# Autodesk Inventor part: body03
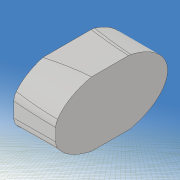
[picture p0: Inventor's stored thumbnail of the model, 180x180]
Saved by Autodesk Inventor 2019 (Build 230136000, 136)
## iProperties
Created: 2020-12
Part Number: body03
Material: 一般
Document SubType Name: Modeling
Designer: kikut
Density: 1 g/cm^3
Appearance: 既定
Mass: 87.6477 g
Surface Area: 156.124 cm^2
Volume: 87.6477 cm^3
Author: kikut
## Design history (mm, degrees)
sketch "スケッチ1"
  geometry: L1 (-100, -20)-(100, -20); L2 (100, -20)-(100, 20); L3 (100, 20)-(-100, 20); L4 (-100, 20)-(-100, -20); L5 (-100, -20)-(100, 20); L6 (100, -20)-(-100, 20); 1 further point
  constraints: 12 end point, 2 midpoint, 2 parallel, 1 horizontal, 1 perpendicular
  dimensions: "d0" = 40 distance of L3.end L1.start; "d1" = 200 distance of L2.end L3.end
extrude "押し出し1" new body sketch "スケッチ1" stored distance "d2" = 60; taper "d3" = 0 deg
sketch "スケッチ2"
  geometry: L1 (0, -60)-(0, 0) reference; L2 (200, -60)-(200, 0) reference; L3 (0, 0)-(200, 0) reference; L4 (200, -60)-(0, -60) reference; L5 (0, -26)-(0, -32); L6 (194, -10)-(194, -13); L7 (194, -13)-(174, -33); L8 (174, -33)-(200, -58); L9 (-20, 20)-(220, 20); L10 (220, 20)-(220, -100); L11 (220, -100)-(-20, -100); L12 (-20, -100)-(-20, 20); 12 further points
  constraints: 16 end point, 4 point on line, 2 parallel, 2 vertical, 1 horizontal, 1 perpendicular, 14 other
  dimensions: "d4" = 32 distance from line of point (32, -12) L1; "d5" = 50 horizontal distance of point (32, -12) point (82, -11); "d6" = 50 horizontal distance of point (132, -17) point (82, -11); "d7" = 12 distance from line of point (32, -12) L3; "d8" = 11 distance from line of point (82, -11) L3; "d10" = 17 distance from line of point (132, -17) L3; "d11" = 26 distance from line of L5.start L3; "d12" = 0 distance from line of point (200, -60) L4; "d13" = 28 distance from line of L5.end L4; "d14" = 12 distance from line of point (28, -48) L4; "d15" = 10 distance from line of point (80, -50) L4; "d16" = 16 distance from line of point (130, -44) L4; "d17" = 28 distance from line of point (28, -48) L1; "d19" = 50 horizontal distance of point (130, -44) point (80, -50); "d20" = 80 distance from line of point (80, -50) L1; "d21" = 6 distance from line of L6.start L2; "d22" = 36 distance from line of point (164, -24) L2; "d23" = 24 distance from line of point (176, -20) L2; "d24" = 10 distance from line of L6.start L3; "d25" = 20 distance from line of point (176, -20) L3; "d26" = 24 distance from line of point (164, -24) L3; "d27" = 40 distance from line of point (160, -40) L2; "d28" = 25 distance from line of point (175, -47.5) L2; "d29" = 12.5 distance from line of point (175, -47.5) L4; "d30" = 20 distance from line of L4 point (160, -40); "d31" = 3 distance of L6.start L6.end; "d32" = 33 distance from line of L7.end L3; "d33" = 26 distance from line of L7.end L2; "d34" = 2 distance of L8.end L2.start; "d35" = 120 distance of L11.end L9.start; "d36" = 240 distance of L10.end L11.end; "d37" = 20 distance between parallel lines of L1 L12; "d38" = 20 distance between parallel lines of L3 L9
extrude "押し出し2" cut sketch "スケッチ2" extent not by distance; stored distance "d39" = 0.02; taper "d40" = 0 deg
sketch "スケッチ8"
  geometry: L1 (-100, -20)-(-100, 20) reference; L2 (100, 20)-(100, -20) reference; L3 (-142.805, 0)-(142.831, 0) reference; L4 (110, 30)-(-110, 30); L5 (-110, 30)-(-110, -30); L6 (-110, -30)-(110, -30); L7 (110, -30)-(110, 30); L8 (110, 30)-(-110, -30); L9 (-110, 30)-(110, -30); L10 (-100, -2)-(-100, 2); L11 (100, -3)-(100, 3); 7 further points
  constraints: 16 end point, 4 point on line, 2 midpoint, 2 parallel, 2 perpendicular, 1 collinear, 1 horizontal, 10 other
  dimensions: "d93" = 2 vertical distance of point (0, 0) L10.end; "d94" = 2 vertical distance of L10.start point (0, 0); "d95" = 35 distance from line of point (-65, -10) L1; "d96" = 0 horizontal distance of point (-65, 10) point (-65, -10); "d97" = 10 vertical distance of point (0, 0) point (-65, -10); "d98" = 10 vertical distance of point (-65, 10) point (0, 0); "d99" = 100 distance from line of point (0, -10) L1; "d100" = 0 horizontal distance of point (0, 10) point (0, -10); "d101" = 10 distance of point (0, -10) point (0, 0); "d102" = 10 distance of point (0, 0) point (0, 10); "d103" = 160 distance from line of point (60, -4) L1; "d104" = 0 horizontal distance of point (60, 4) point (60, -4); "d105" = 4 distance from line of L3 point (60, -4); "d106" = 4 distance from line of L3 point (60, 4); "d107" = 3 distance from line of L11.start L3; "d108" = 3 distance from line of L11.end L3; "d109" = 220 distance of L5.end L6.end; "d110" = 60 distance of L4.end L5.end
extrude "押し出し6" cut sketch "スケッチ8" extent not by distance; stored distance "d111" = 10; taper "d112" = 0 deg
sketch "スケッチ9" dims "d113" = 20, "d114" = 12
  geometry: L1 (-29, -18)-(21, -18); L2 (21, -18)-(21, 22); L3 (21, 22)-(-29, 22); L4 (-29, 22)-(-29, -18); L5 (-29, -18)-(21, 22); L6 (21, -18)-(-29, 22); 2 further points; 1 other entity
  constraints: 12 end point, 2 midpoint, 2 parallel, 1 coincident, 1 horizontal, 1 perpendicular, 2 other
  dimensions: "d115" = 50 distance of L2.end L3.end; "d116" = 40 distance of L1.end L2.end
extrude "押し出し7" cut sketch "スケッチ9" distance "d117" = 150; taper "d118" = 0 deg
fillet "フィレット4" dims "d119" = 4
fillet "フィレット5" dims "d120" = 4
fillet "フィレット6" dims "d121" = 2
node "作業平面2"
sketch "スケッチ10"
  geometry: L1 (0, -41.439)-(0, 38.458) reference; L2 (141.833, 0)-(-140.631, 0) reference; L3 (82.55, 12.983)-(81.45, -4.983); A1 r 9 centre (82, 4) between (82.55, 12.983) and (81.45, -4.983); 1 further point
  constraints: 2 end point, 2 point on circle, 1 centre point
  dimensions: "d123" = 82 distance from line of L1 A1.centre; "d124" = 4 distance from line of L2 A1.centre; "d125" = 9 radius of A1; "d126" = 180 deg dimension on A1.centre L3.end L3.start; "d127" = 90 deg dimension on L3.end point (0, 0) A1.centre
revolve "回転1" sketch "スケッチ10" stored, may be unused: angle "d128" = 90 deg
mirror "ミラー1"
sketch "スケッチ11"
  geometry: L1 (55, 30)-(40, 30); L2 (40, 30)-(40, -30); L3 (40, -30)-(55, -30); L4 (55, -30)-(55, 30); L5 (0, -40.648)-(0, 34.486) reference; L6 (140.69, 0)-(-139.196, 0) reference; L7 (120, 53.792)-(-120, 53.792); L8 (-120, 53.792)-(-120, -46.208); L9 (-120, -46.208)-(120, -46.208); L10 (120, -46.208)-(120, 53.792); 1 further point
  constraints: 16 end point, 4 parallel, 2 horizontal, 2 perpendicular, 2 other
  dimensions: "d129" = 40 distance between parallel lines of L5 L2; "d130" = 15 distance of L1.start L1.end; "d131" = 60 distance of L3.end L1.start; "d132" = 100 distance of L9.end L7.start; "d133" = 240 distance of L7.start L7.end
extrude "押し出し8" cut sketch "スケッチ11" stored distance "d134" = 40; taper "d135" = 0 deg
node "ソリッド1"
other parameters: "d122" = -1
